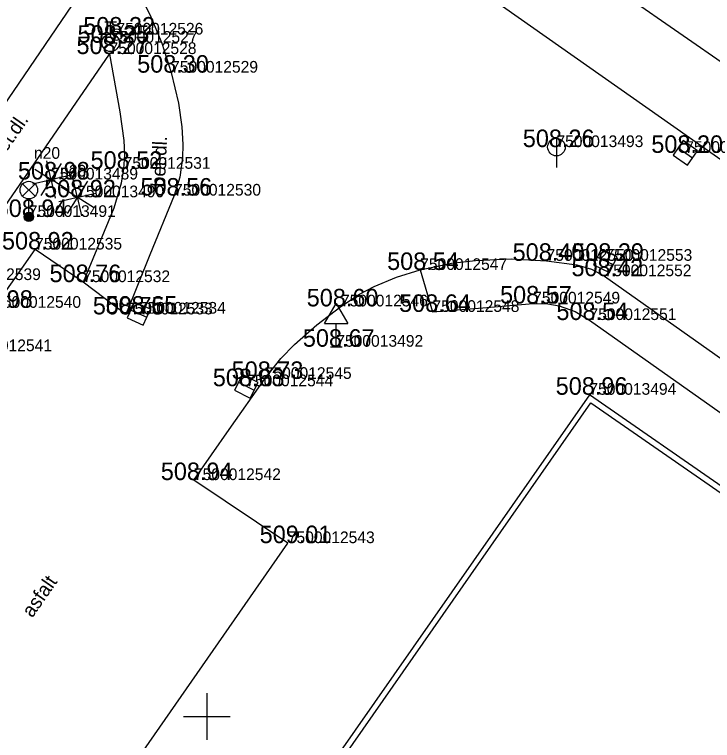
# Model space of a CAD drawing. Extents: x -669251 to -668549, y -1128351 to -1127698.
# Drawn here: x -668858.22 to -668828.37, y -1127851.02 to -1127819.96 of the extents above; entities that cross this region are included whole.
import ezdxf

# ---------------------------------------------------------------- set-up
doc = ezdxf.new("R2010")
doc.units = 0
for name, color, linetype in [('Vrstva 1', 7, 'Continuous'), ('Vrstva 10', 7, 'Continuous'), ('Vrstva 2', 7, 'Continuous'), ('Vrstva 22', 7, 'Continuous'), ('Vrstva 27', 7, 'Continuous'), ('Vrstva 28', 7, 'Continuous'), ('Vrstva 3', 7, 'Continuous'), ('Vrstva 33', 7, 'Continuous'), ('Vrstva 34', 7, 'Continuous'), ('Vrstva 40', 7, 'Continuous'), ('Vrstva 47', 7, 'Continuous'), ('Vrstva 61', 7, 'Continuous'), ('Vrstva 7', 7, 'Continuous')]:
    doc.layers.add(name, color=color, linetype=linetype)

msp = doc.modelspace()

# ---------------------------------------------------------------- linework, layer by layer
at = {"layer": 'Vrstva 1'}
for p, q in [((-668853.868, -1127820.818), (-668853.868, -1127820.818)), ((-668854.114, -1127821.168), (-668854.114, -1127821.168)), ((-668854.159, -1127821.653), (-668854.159, -1127821.653)), ((-668851.527, -1127822.448), (-668851.527, -1127822.448)), ((-668835.045, -1127825.633), (-668835.045, -1127825.633)), ((-668829.535, -1127825.881), (-668829.535, -1127825.881)), ((-668853.557, -1127826.562), (-668853.557, -1127826.562)), ((-668856.661, -1127827.019), (-668856.661, -1127827.019)), ((-668855.541, -1127827.781), (-668855.541, -1127827.781)), ((-668851.399, -1127827.709), (-668851.399, -1127827.709)), ((-668857.612, -1127828.623), (-668857.612, -1127828.623)), ((-668857.344, -1127830.016), (-668857.344, -1127830.016)), ((-668835.467, -1127830.5), (-668835.467, -1127830.5)), ((-668832.952, -1127830.499), (-668832.952, -1127830.499)), ((-668840.871, -1127830.891), (-668840.871, -1127830.891)), ((-668832.987, -1127831.157), (-668832.987, -1127831.157)), ((-668855.288, -1127831.411), (-668855.288, -1127831.411)), ((-668844.261, -1127832.45), (-668844.261, -1127832.45)), ((-668836.04, -1127832.326), (-668836.04, -1127832.326)), ((-668853.46, -1127832.792), (-668853.46, -1127832.792)), ((-668852.905, -1127832.76), (-668852.905, -1127832.76)), ((-668840.346, -1127832.686), (-668840.346, -1127832.686)), ((-668833.63, -1127833.033), (-668833.63, -1127833.033)), ((-668844.462, -1127834.176), (-668844.462, -1127834.176)), ((-668847.522, -1127835.553), (-668847.522, -1127835.553)), ((-668848.314, -1127835.867), (-668848.314, -1127835.867)), ((-668833.635, -1127836.231), (-668833.635, -1127836.231)), ((-668850.55, -1127839.882), (-668850.55, -1127839.882)), ((-668846.536, -1127842.58), (-668846.536, -1127842.58))]:
    msp.add_line(p, q, dxfattribs=at)
at = {"layer": 'Vrstva 10'}
for p, q in [((-668839.985, -1127817.748), (-668808.868, -1127839.638)), ((-668855.496, -1127819.148), (-668862.836, -1127829.926)), ((-668860.815, -1127831.323), (-668854.159, -1127821.653)), ((-668859.096, -1127832.509), (-668857.344, -1127830.016)), ((-668855.288, -1127831.411), (-668857.344, -1127830.016)), ((-668840.871, -1127830.891), (-668840.346, -1127832.686)), ((-668853.46, -1127832.792), (-668855.288, -1127831.411)), ((-668846.536, -1127842.58), (-668850.55, -1127839.882)), ((-668857.925, -1127858.941), (-668846.536, -1127842.58))]:
    msp.add_line(p, q, dxfattribs=at)
for points in [[(-668856.591, -1127814.83), (-668856.366, -1127815.005), (-668856.141, -1127815.18), (-668855.507, -1127815.725), (-668854.643, -1127816.636), (-668853.835, -1127817.637), (-668853.433, -1127818.193), (-668852.818, -1127819.2), (-668852.425, -1127819.981), (-668851.928, -1127821.193), (-668851.527, -1127822.448), (-668851.211, -1127823.76), (-668851.062, -1127824.77), (-668851.02, -1127825.528), (-668851.038, -1127826.091), (-668851.155, -1127826.917), (-668851.399, -1127827.709), (-668852.43, -1127830.25), (-668853.46, -1127832.792)], [(-668854.159, -1127821.653), (-668853.716, -1127824.123), (-668853.548, -1127825.352), (-668853.524, -1127825.96), (-668853.557, -1127826.562), (-668853.661, -1127827.181), (-668853.978, -1127828.248), (-668855.288, -1127831.411)], [(-668850.55, -1127839.882), (-668849.036, -1127837.718), (-668847.522, -1127835.553), (-668846.827, -1127834.679), (-668846.246, -1127834.078), (-668845.293, -1127833.241), (-668844.261, -1127832.45), (-668843.463, -1127831.929), (-668842.844, -1127831.603), (-668841.88, -1127831.203), (-668840.871, -1127830.891), (-668839.527, -1127830.606), (-668838.51, -1127830.479), (-668836.982, -1127830.418), (-668835.467, -1127830.5), (-668834.173, -1127830.675), (-668833.551, -1127830.858), (-668832.987, -1127831.157), (-668824.136, -1127837.414), (-668815.284, -1127843.67)], [(-668840.346, -1127832.686), (-668838.193, -1127832.506), (-668836.04, -1127832.326), (-668835.408, -1127832.339), (-668834.934, -1127832.428), (-668834.25, -1127832.674), (-668833.63, -1127833.033), (-668818.127, -1127843.993), (-668808.189, -1127851.019)]]:
    msp.add_lwpolyline(points, dxfattribs=at)
at = {"layer": 'Vrstva 22'}
for p, q in [((-668856.669, -1127826.979), (-668856.841, -1127826.225)), ((-668856.227, -1127826.329), (-668856.641, -1127826.985)), ((-668856.695, -1127826.999), (-668857.351, -1127826.585)), ((-668856.621, -1127827.011), (-668855.867, -1127826.839)), ((-668855.549, -1127827.741), (-668855.721, -1127826.987)), ((-668857.455, -1127827.199), (-668856.701, -1127827.027)), ((-668856.681, -1127827.053), (-668857.095, -1127827.709)), ((-668856.653, -1127827.059), (-668856.481, -1127827.813)), ((-668855.971, -1127827.453), (-668856.627, -1127827.039)), ((-668855.107, -1127827.091), (-668855.521, -1127827.747)), ((-668855.575, -1127827.761), (-668856.231, -1127827.347)), ((-668855.501, -1127827.773), (-668854.747, -1127827.601)), ((-668856.335, -1127827.961), (-668855.581, -1127827.789)), ((-668855.561, -1127827.815), (-668855.975, -1127828.471)), ((-668855.533, -1127827.821), (-668855.361, -1127828.575)), ((-668854.851, -1127828.215), (-668855.507, -1127827.801))]:
    msp.add_line(p, q, dxfattribs=at)
for centre in [(-668856.661, -1127827.019), (-668855.541, -1127827.781)]:
    msp.add_circle(centre, 0.04, dxfattribs=at)
at = {"layer": 'Vrstva 27'}
for p, q in [((-668835.045, -1127825.258), (-668835.045, -1127826.508)), ((-668829.843, -1127825.667), (-668829.227, -1127826.095)), ((-668833.29, -1127830.337), (-668832.614, -1127830.661)), ((-668853.247, -1127832.606), (-668852.563, -1127832.914)), ((-668848.648, -1127835.697), (-668847.98, -1127836.037))]:
    msp.add_line(p, q, dxfattribs=at)
for points in [[(-668830.056, -1127825.974), (-668829.441, -1127826.402), (-668829.012, -1127825.786), (-668829.628, -1127825.358)], [(-668833.452, -1127830.674), (-668832.775, -1127830.998), (-668832.451, -1127830.322), (-668833.128, -1127829.998)], [(-668853.401, -1127832.946), (-668852.717, -1127833.255), (-668852.408, -1127832.572), (-668853.092, -1127832.263)], [(-668848.818, -1127836.03), (-668848.15, -1127836.371), (-668847.809, -1127835.703), (-668848.477, -1127835.362)]]:
    msp.add_lwpolyline(points, close=True, dxfattribs=at)
msp.add_circle((-668835.045, -1127825.633), 0.375, dxfattribs=at)
at = {"layer": 'Vrstva 28'}
for p, q in [((-668854.364, -1127820.268), (-668853.864, -1127820.268)), ((-668854.114, -1127820.793), (-668854.114, -1127820.268)), ((-668854.118, -1127820.818), (-668854.618, -1127820.818)), ((-668854.379, -1127821.433), (-668853.849, -1127820.903)), ((-668853.618, -1127820.818), (-668853.118, -1127820.818))]:
    msp.add_line(p, q, dxfattribs=at)
for centre, radius in [((-668854.114, -1127821.168), 0.375), ((-668853.868, -1127820.818), 0.25)]:
    msp.add_circle(centre, radius, dxfattribs=at)
at = {"layer": 'Vrstva 33'}
for p, q in [((-668857.877, -1127827.208), (-668857.347, -1127827.738)), ((-668857.877, -1127827.738), (-668857.347, -1127827.208)), ((-668857.612, -1127828.623), (-668857.612, -1127827.848))]:
    msp.add_line(p, q, dxfattribs=at)
for centre, radius in [((-668857.612, -1127827.473), 0.375), ((-668857.612, -1127828.623), 0.2), ((-668857.612, -1127828.623), 0.18), ((-668857.612, -1127828.623), 0.16), ((-668857.612, -1127828.623), 0.14), ((-668857.612, -1127828.623), 0.12), ((-668857.612, -1127828.623), 0.1), ((-668857.612, -1127828.623), 0.08), ((-668857.612, -1127828.623), 0.06), ((-668857.612, -1127828.623), 0.04), ((-668857.612, -1127828.623), 0.02)]:
    msp.add_circle(centre, radius, dxfattribs=at)
at = {"layer": 'Vrstva 34'}
for p, q in [((-668844.962, -1127833.176), (-668844.462, -1127832.326)), ((-668844.462, -1127832.326), (-668843.962, -1127833.176)), ((-668844.962, -1127833.176), (-668843.962, -1127833.176)), ((-668844.462, -1127834.176), (-668844.462, -1127833.176)), ((-668844.712, -1127834.176), (-668844.212, -1127834.176))]:
    msp.add_line(p, q, dxfattribs=at)
at = {"layer": 'Vrstva 61'}
for p, q in [((-668850, -1127849), (-668850, -1127851)), ((-668851, -1127850), (-668849, -1127850))]:
    msp.add_line(p, q, dxfattribs=at)
at = {"layer": 'Vrstva 7'}
for p, q in [((-668824.114, -1127824.707), (-668835.374, -1127816.87)), ((-668833.635, -1127836.231), (-668847.677, -1127856.35)), ((-668820.476, -1127845.369), (-668833.635, -1127836.231)), ((-668847.472, -1127856.493), (-668833.573, -1127836.579)), ((-668833.573, -1127836.579), (-668820.618, -1127845.575))]:
    msp.add_line(p, q, dxfattribs=at)

# ---------------------------------------------------------------- texts
at = {"layer": 'Vrstva 2'}
for s, p in [('7500012526', (-668853.868, -1127820.818)), ('7500012527', (-668854.114, -1127821.168)), ('7500012528', (-668854.159, -1127821.653)), ('7500012529', (-668851.527, -1127822.448)), ('7500013493', (-668835.045, -1127825.633)), ('7500012554', (-668829.535, -1127825.881)), ('7500012531', (-668853.557, -1127826.562)), ('7500013489', (-668856.661, -1127827.019)), ('7500013490', (-668855.541, -1127827.781)), ('7500012530', (-668851.399, -1127827.709)), ('7500013491', (-668857.612, -1127828.623)), ('7500012535', (-668857.344, -1127830.016)), ('7500012550', (-668835.467, -1127830.5)), ('7500012553', (-668832.952, -1127830.499)), ('7500012547', (-668840.871, -1127830.891)), ('7500012552', (-668832.987, -1127831.157)), ('7500012539', (-668860.815, -1127831.323)), ('7500012532', (-668855.288, -1127831.411)), ('7500012546', (-668844.261, -1127832.45)), ('7500012549', (-668836.04, -1127832.326)), ('7500012540', (-668859.096, -1127832.509)), ('7500012533', (-668853.46, -1127832.792)), ('7500012534', (-668852.905, -1127832.76)), ('7500012548', (-668840.346, -1127832.686)), ('7500012551', (-668833.63, -1127833.033)), ('7500013492', (-668844.462, -1127834.176)), ('7500012541', (-668860.339, -1127834.366)), ('7500012545', (-668847.522, -1127835.553)), ('7500012544', (-668848.314, -1127835.867)), ('7500013494', (-668833.635, -1127836.231)), ('7500012542', (-668850.55, -1127839.882)), ('7500012543', (-668846.536, -1127842.58))]:
    msp.add_text(s, height=0.5, dxfattribs=at).set_placement(p)
at = {"layer": 'Vrstva 3'}
for s, p in [('508.22 ', (-668855.283, -1127820.818)), ('508.25 ', (-668855.529, -1127821.168)), ('508.27 ', (-668855.574, -1127821.653)), ('508.30 ', (-668852.978, -1127822.448)), ('508.26 ', (-668836.483, -1127825.633)), ('508.20 ', (-668830.986, -1127825.881)), ('508.52 ', (-668854.972, -1127826.562)), ('508.98 ', (-668858.078, -1127827.019)), ('508.56 ', (-668852.837, -1127827.709)), ('508.92 ', (-668856.958, -1127827.781)), ('508.94 ', (-668859.029, -1127828.623)), ('508.92 ', (-668858.761, -1127830.016)), ('508.40 ', (-668836.918, -1127830.5)), ('508.29 ', (-668834.37, -1127830.499)), ('508.54 ', (-668842.286, -1127830.891)), ('508.42 ', (-668834.402, -1127831.157)), ('508.76 ', (-668856.726, -1127831.411)), ('508.57 ', (-668837.455, -1127832.326)), ('508.98 ', (-668860.513, -1127832.509)), ('508.60 ', (-668845.725, -1127832.45)), ('508.64 ', (-668841.775, -1127832.686)), ('508.75 ', (-668854.875, -1127832.792)), ('508.65 ', (-668854.334, -1127832.76)), ('508.54 ', (-668835.045, -1127833.033)), ('508.67 ', (-668845.891, -1127834.176)), ('508.73 ', (-668848.937, -1127835.553)), ('508.63 ', (-668849.743, -1127835.867)), ('508.96 ', (-668835.075, -1127836.231)), ('508.94 ', (-668851.967, -1127839.882)), ('509.01 ', (-668847.738, -1127842.58))]:
    msp.add_text(s, height=0.75, dxfattribs=at).set_placement(p)
at = {"layer": 'Vrstva 40'}
for s, rotation, p in [('bet.dl.', 55.0494, (-668858.847, -1127826.25)), ('bet.dl.', 87.5005, (-668851.791, -1127827.352)), ('asfalt', 55.1306, (-668857.468, -1127845.805))]:
    msp.add_text(s, height=0.6, rotation=rotation, dxfattribs=at).set_placement(p)
at = {"layer": 'Vrstva 47'}
for p in [(-668857.391, -1127826.133), (-668856.271, -1127826.895)]:
    msp.add_text('n20', height=0.5, dxfattribs=at).set_placement(p)

doc.saveas('drawing.dxf')
